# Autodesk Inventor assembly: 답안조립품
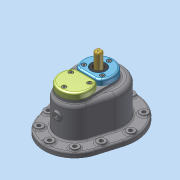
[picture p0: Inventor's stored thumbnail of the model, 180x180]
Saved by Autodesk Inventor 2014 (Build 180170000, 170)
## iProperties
Created: 2026-08
Part Number: 답안조립품
Document SubType Name: Assembly
Designer: dg
Author: dg
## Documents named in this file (14)
- C:\Users\dg\Desktop\660803V1004\답안조립품.iam
- C:\Users\dg\Desktop\660803V1004\가져온 구성요소\본체\본체.ipt
- C:\Users\dg\Desktop\660803V1004\가져온 구성요소\깊은 홈 볼 베어링 6001\깊은 홈 볼 베어링 6001.ipt
- C:\Users\dg\Desktop\660803V1004\가져온 구성요소\C형 멈춤링 구멍용 28\C형 멈춤링 구멍용 28.ipt
- C:\Users\dg\Desktop\660803V1004\가져온 구성요소\스퍼 기어\스퍼 기어.ipt
- C:\Users\dg\Desktop\660803V1004\가져온 구성요소\축\축.ipt
- C:\Users\dg\Desktop\660803V1004\가져온 구성요소\평행 키 4x4x12\평행 키 4x4x12.ipt
- C:\Users\dg\Desktop\660803V1004\가져온 구성요소\C형 멈춤링 축용 12\C형 멈춤링 축용 12.ipt
- C:\Users\dg\Desktop\660803V1004\가져온 구성요소\칼라\칼라.ipt
- C:\Users\dg\Desktop\660803V1004\가져온 구성요소\기어 축\기어 축.ipt
- C:\Users\dg\Desktop\660803V1004\가져온 구성요소\상부 커버\상부 커버.ipt
- C:\Users\dg\Desktop\660803V1004\가져온 구성요소\오일 실 12 25 7\오일 실 12 25 7.ipt
- C:\Users\dg\Desktop\660803V1004\가져온 구성요소\하부 커버\하부 커버.ipt
- C:\Users\dg\Desktop\660803V1004\가져온 구성요소\6각 구멍붙이 볼트 M4x10\6각 구멍붙이 볼트 M4x10.ipt
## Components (10 placed, 4 different names)
1. C형 멈춤링 구멍용 28:1
2. C형 멈춤링 축용 12:1
3. C형 멈춤링 축용 12:2
4. 하부 커버:1
5. 6각 구멍붙이 볼트 M4x10:1
6. 6각 구멍붙이 볼트 M4x10:3
7. 6각 구멍붙이 볼트 M4x10:4
8. 6각 구멍붙이 볼트 M4x10:2
9. 6각 구멍붙이 볼트 M4x10:5
10. 6각 구멍붙이 볼트 M4x10:6
